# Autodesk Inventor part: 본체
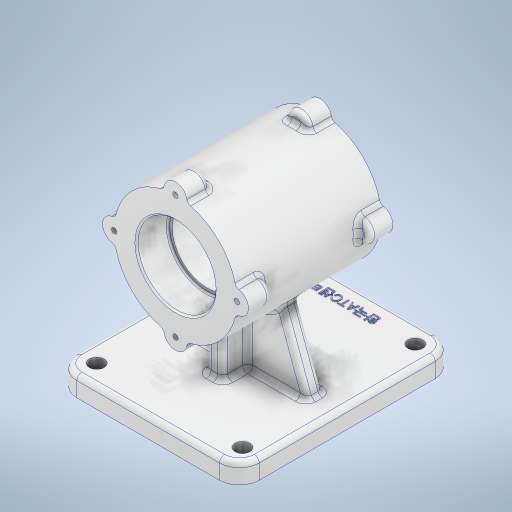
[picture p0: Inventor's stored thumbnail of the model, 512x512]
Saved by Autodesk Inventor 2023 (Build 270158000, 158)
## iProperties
Created: 2023-08
Part Number: 본체
Material: 알루미늄 6061
Document SubType Name: Modeling
Designer: asung
Density: 2.7 g/cm^3
Appearance: 알루미늄 - 평지
Author: asung
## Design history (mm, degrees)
sketch "스케치1"
  geometry: L1 (43, 65)-(-43, 65); L2 (-55, 53)-(-55, -53); L3 (-43, -65)-(43, -65); L4 (55, -53)-(55, 53); L5 (55, 65)-(-55, -65); L6 (-55, 65)-(55, -65); C1 r 4.5 at (43, -53); C2 r 4.5 at (43, 53); C3 r 4.5 at (-44.846, 53); C4 r 4.5 at (-43, -53); A1 r 12 centre (43, -53) between (43, -65) and (55, -53); A2 r 12 centre (43, 53) between (55, 53) and (43, 65); A3 r 12 centre (-43, 53) between (-43, 65) and (-55, 53); A4 r 12 centre (-43, -53) between (-55, -53) and (-43, -65); 1 further point
  constraints: 12 end point, 9 point on line, 8 centre point, 8 point on circle, 8 tangent, 3 coincident, 3 equal radius, 2 midpoint, 2 parallel, 1 horizontal, 1 perpendicular
  dimensions: "d0" = 110 distance of L6.end L5.end; "d1" = 130 distance of L5.end L6.start; "d2" = 12 radius of A1; "d3" = 9 diameter of C1; "d4" = 9 diameter of C2; "d5" = 9 diameter of C3; "d6" = 9 diameter of C4
extrude "돌출1" new body sketch "스케치1" distance "d7" = 12; taper "d8" = 0 deg
node "작업 평면1"
node "작업 평면2"
sketch "스케치2"
  geometry: L1 (98, 12)-(98, 0) reference; L2 (98, 0)-(-12, 0) reference; L3 (-12, 0)-(-12, 12) reference; L4 (-12, 12)-(98, 12) reference; L5 (43, 0)-(43, 82); L6 (43, 82)-(43, 52.403); L7 (43, -29.598)-(130, -29.598); C1 r 37 at (43, 82)
  constraints: 6 end point, 2 point on line, 1 centre point, 1 coincident, 1 horizontal, 1 vertical
  dimensions: "d10" = 82 distance of L5.start L5.end; "d11" = 87 distance of L7.start L7.end; "d12" = 37 radius of C1
extrude "돌출2" join sketch "스케치2" distance "d13" = 53.5; taper "d14" = 0 deg; dims "d65" = 33.5, "d66" = 0
sketch "스케치3"
  geometry: C1 r 7 at (0, 37); 6 further points
  constraints: 2 coincident, 1 centre point, 2 other
  dimensions: "d15" = 7 radius of C1
extrude "돌출3" join sketch "스케치3" distance "d16" = 14; taper "d17" = 0 deg
sketch "스케치4"
  geometry: A1 r 7 centre (43, 119) between (49.969, 118.338) and (36.031, 118.338) reference; 2 further points
  constraints: 1 coincident
hole "구멍1" sketch "스케치4" at (43, 119) diameter "d18" = 3.242; stored, may be unused: countersink angle "d22" = 90 deg, drill point angle "d24" = 118 deg; dims "d19" = 8, "d20" = 4, "d21" = 2, "d23" = 10
fillet "모깎기1" dims "d25" = 3
node "작업 평면3"
sketch "스케치6"
  geometry: A1 r 37 centre (-43, 82) between (-52.104, 117.863) and (-78.862, 91.104) reference; 4 further points
  constraints: 1 coincident
hole "구멍2" sketch "스케치6" at (-43, 82) diameter "d30" = 42; stored, may be unused: countersink angle "d34" = 90 deg, drill point angle "d36" = 118 deg; dims "d31" = 8, "d32" = 47, "d33" = 19, "d35" = 45
sketch "스케치7"
  geometry: A1 r 37 centre (43, 82) between (33.896, 117.863) and (7.137, 91.104) reference; 4 further points
  constraints: 1 coincident
hole "구멍3" sketch "스케치7" at (43, 82) diameter "d37" = 42; stored, may be unused: countersink angle "d41" = 90 deg, drill point angle "d43" = 118 deg; dims "d38" = 6, "d39" = 47, "d40" = 19, "d42" = 45
chamfer "모따기1" distance "d45" = 1; stored, may be unused: second distance "d46" = 2, angle "d47" = 45 deg
fillet "모깎기3" dims "d48" = 1
node "작업 평면4"
sketch "스케치8"
  geometry: L1 (-43, 65)-(43, 65) reference; L2 (55, 53)-(55, -53) reference; L3 (43, -65)-(-43, -65) reference; L4 (-55, -53)-(-55, 53) reference; L5 (5, 20)-(-5, 20); L6 (-5, 20)-(-5, -20); L7 (-5, -20)-(5, -20); L8 (5, -20)-(5, 20); L9 (5, 20)-(-5, -20); L10 (-5, 20)-(5, -20); C1 r 4.5 at (43, -53) reference; C2 r 4.5 at (43, 53) reference; C3 r 4.5 at (-44.846, 53) reference; C4 r 4.5 at (-43, -53) reference; A1 r 12 centre (43, 53) between (55, 53) and (43, 65) reference; A2 r 12 centre (43, -53) between (43, -65) and (55, -53) reference; A3 r 12 centre (-43, -53) between (-55, -53) and (-43, -65) reference; A4 r 12 centre (-43, 53) between (-43, 65) and (-55, 53) reference; 1 further point
  constraints: 12 end point, 2 midpoint, 2 parallel, 1 horizontal, 1 perpendicular
  dimensions: "d50" = 40 distance of L6.end L5.end; "d51" = 10 distance of L5.start L5.end
  node "절단 모서리 투영2"
fillet "모깎기4" dims "d54" = 3
sketch "스케치9"
  geometry: L1 (-52, -70)-(52, -70) reference; L2 (55, -73)-(55, -82) reference; L3 (55, -82)-(-55, -82) reference; L4 (-55, -82)-(-55, -73) reference; L5 (-43, -82)-(-55, -82) reference; L6 (-55, -82)-(-40.858, -82); L7 (43, -82)-(-43, -82) reference; L8 (-55, -82)-(-41, -82); L9 (-38.163, -74.206)-(-20.228, -24.929); L10 (0, -30.602)-(0, -82); L11 (38.163, -74.206)-(20.228, -24.929); L12 (-20.228, -24.929)-(-6.969, -29.755); L13 (-6.969, -29.755)-(20.228, -24.929); L14 (-38.163, -74.206)-(38.163, -74.206); C1 r 37 at (0, 0) reference; C2 r 21 at (0, 0) reference; A1 r 3 centre (-52, -73) between (-52, -70) and (-55, -73) reference; A2 r 3 centre (52, -73) between (55, -73) and (52, -70) reference; 1 further point
  constraints: 16 end point, 3 point on line, 2 symmetric about line, 1 horizontal, 1 vertical
  dimensions: "d55" = 14 distance of L3.end L8.end; "d56" = 110 deg angle of L9 L8
  node "절단 모서리 투영3"
sketch "스케치10"
  geometry: L1 (-52, -53)-(-52, 53) reference; L2 (-52, 0)-(-52, 58); L3 (-52, 58)-(0, 58); 2 further points
  constraints: 4 end point, 1 coincident, 1 collinear, 1 midpoint, 1 perpendicular
  dimensions: "d61" = 58 distance of L2.start L2.end
sketch "스케치11"
  geometry: L1 (-47.091, 5.14)-(-47.091, 63.14); 1 further point
  constraints: 2 end point, 1 vertical
  dimensions: "d62" = 58 distance of L1.start L1.end
node "작업 평면5"
sketch "스케치12"
  geometry: L1 (90.526, 45)-(91.5, 43.379) reference; L2 (91.5, 43.379)-(101.5, 43.379) reference; L3 (101.5, 43.379)-(101.5, 38) reference; L4 (101.5, 38)-(90.5, 38) reference; L5 (87.5, 41)-(87.5, 42) reference; L6 (84.5, 45)-(31.5, 45) reference; L7 (-9, 12)-(115, 12) reference; L8 (118, 9)-(118, 0) reference; L9 (118, 0)-(-12, 0) reference; L10 (-12, 0)-(-12, 9) reference; L11 (28.5, 42)-(28.5, 41) reference; L12 (25.5, 38)-(14.5, 38) reference; L13 (14.5, 38)-(14.5, 43.379) reference; L14 (14.5, 43.379)-(24.5, 43.379) reference; L15 (24.5, 43.379)-(25.474, 45) reference; L16 (25.474, 45)-(24.5, 46.621) reference; L17 (24.5, 46.621)-(14.5, 46.621) reference; L18 (14.5, 46.621)-(14.5, 57.5) reference; L19 (14.5, 57.5)-(15.5, 58.5) reference; L20 (15.5, 58.5)-(32.5, 58.5) reference; L21 (33.5, 59.5)-(33.5, 61) reference; L22 (33.5, 61)-(82.5, 61) reference; L23 (82.5, 61)-(82.5, 59.5) reference; L24 (83.5, 58.5)-(100.5, 58.5) reference; L25 (100.5, 58.5)-(101.5, 57.5) reference; L26 (101.5, 57.5)-(101.5, 46.621) reference; L27 (101.5, 46.621)-(91.5, 46.621) reference; L28 (91.5, 46.621)-(90.526, 45) reference; L29 (91.5, 120.621)-(90.526, 119) reference; L30 (90.526, 119)-(91.5, 117.379) reference; L31 (91.5, 117.379)-(101.5, 117.379) reference; L32 (101.5, 117.379)-(101.5, 106.5) reference; L33 (101.5, 106.5)-(100.5, 105.5) reference; L34 (100.5, 105.5)-(83.5, 105.5) reference; L35 (82.5, 104.5)-(82.5, 103) reference; L36 (82.5, 103)-(33.5, 103) reference; L37 (33.5, 103)-(33.5, 104.5) reference; L38 (32.5, 105.5)-(15.5, 105.5) reference; L39 (15.5, 105.5)-(14.5, 106.5) reference; L40 (14.5, 106.5)-(14.5, 117.379) reference; L41 (14.5, 117.379)-(24.5, 117.379) reference; L42 (24.5, 117.379)-(25.474, 119) reference; L43 (25.474, 119)-(24.5, 120.621) reference; L44 (24.5, 120.621)-(14.5, 120.621) reference; L45 (14.5, 120.621)-(14.5, 126) reference; L46 (14.5, 126)-(25.5, 126) reference; L47 (28.5, 123)-(28.5, 122) reference; L48 (31.5, 119)-(84.5, 119) reference; L49 (87.5, 122)-(87.5, 123) reference; L50 (90.5, 126)-(101.5, 126) reference; L51 (101.5, 126)-(101.5, 120.621) reference; L52 (101.5, 120.621)-(91.5, 120.621) reference; L53 (38, 54.414)-(78, 54.414); L54 (78, 54.414)-(78, 5.894); L55 (78, 5.894)-(38, 5.894); L56 (38, 5.894)-(38, 54.414); A1 r 3 centre (90.5, 41) between (87.5, 41) and (90.5, 38) reference; A2 r 3 centre (84.5, 42) between (87.5, 42) and (84.5, 45) reference; A3 r 3 centre (115, 9) between (118, 9) and (115, 12) reference; A4 r 3 centre (-9, 9) between (-9, 12) and (-12, 9) reference; A5 r 3 centre (31.5, 42) between (31.5, 45) and (28.5, 42) reference; A6 r 3 centre (25.5, 41) between (25.5, 38) and (28.5, 41) reference; A7 r 1 centre (32.5, 59.5) between (32.5, 58.5) and (33.5, 59.5) reference; A8 r 1 centre (83.5, 59.5) between (82.5, 59.5) and (83.5, 58.5) reference; A9 r 1 centre (83.5, 104.5) between (83.5, 105.5) and (82.5, 104.5) reference; A10 r 1 centre (32.5, 104.5) between (33.5, 104.5) and (32.5, 105.5) reference; A11 r 3 centre (25.5, 123) between (28.5, 123) and (25.5, 126) reference; A12 r 3 centre (31.5, 122) between (28.5, 122) and (31.5, 119) reference; A13 r 3 centre (84.5, 122) between (84.5, 119) and (87.5, 122) reference; A14 r 3 centre (90.5, 123) between (90.5, 126) and (87.5, 123) reference; 5 further points
  constraints: 8 end point, 2 parallel, 1 horizontal, 1 perpendicular
  dimensions: "d63" = 40 distance of L54.end L55.end; "d64" = 50 distance from line of L9.end L56
  node "절단 모서리 투영4"
node "작업 평면6"
sketch "스케치13"
  geometry: 1 further point
extrude "돌출7" join sketch "스케치12" stored distance "d69" = 10; taper "d70" = 0 deg
sketch "스케치14"
  geometry: L1 (-95, 12)-(-48, 12) reference; L2 (-48, 12)-(-48, 45.339) reference; L3 (-38, 45.339)-(-38, 12) reference; L4 (-38, 12)-(9, 12) reference; L5 (12, 9)-(12, 0) reference; L6 (12, 0)-(-98, 0) reference; L7 (-98, 0)-(-98, 9) reference; L8 (-98, 0)-(-98, 9) reference; L9 (-98, 9)-(-84, 9); L10 (-84, 9)-(-84, 12); L11 (-92.346, 12)-(-83.346, 12) reference; L12 (-84, 12)-(-63.719, 67.721); L13 (-43, 82)-(-43, 75.844); L14 (-2, 12)-(-22.281, 67.721); L15 (-63.719, 67.721)-(-48, 50.336); L16 (-48, 50.336)-(-37.401, 54.049); L17 (-37.401, 54.049)-(-22.281, 67.721); L18 (-84, 12)-(-2, 12); L19 (-86, 12)-(0, 12) reference; C1 r 21 at (-43, 82) reference; A1 r 3 centre (-95, 9) between (-95, 12) and (-98, 9) reference; A2 r 37 centre (-43, 82) between (-38, 45.339) and (-48, 45.339) reference; A3 r 3 centre (9, 9) between (12, 9) and (9, 12) reference; 5 further points
  constraints: 18 end point, 2 perpendicular, 2 symmetric about line, 1 collinear, 1 horizontal, 1 point on line, 1 vertical
  dimensions: "d71" = 14 distance of L7.end L9.end; "d72" = 110 deg angle of L12 L11
extrude "돌출8" join sketch "스케치14" stored distance "d73" = 10; taper "d74" = 0 deg
fillet "모깎기7" dims "d75" = 3
fillet "모깎기8" dims "d76" = 3
sketch "스케치16"
  geometry: L1 (-43, -65)-(43, -65) reference; 2 further points
  constraints: 1 vertical alignment, 1 other
  dimensions: "d81" = 118 distance from line of point (0, 53) L1
feature "엠보싱2" sketch "스케치16" dims "d0" = 110, "d1" = 130, "d2" = 12, "d3" = 9, "d4" = 9, "d5" = 9, "d6" = 9, "d82" = 0.5, "d83" = 0
feature "ӌ耀ӎ耀Ӑ耀Ӓ耀Ӕ耀Ӗ耀Ә耀Ӛ耀" dims "d0" = 110, "d1" = 130, "d2" = 12, "d3" = 9, "d4" = 9, "d5" = 9, "d6" = 9, "d7" = 12, "d8" = 0, "d9" = -70, "d10" = 82, "d11" = 87, "d12" = 37, "d13" = 53.5, "d14" = 0, "d15" = 7, "d16" = 14, "d17" = 0, "d18" = 3.242, "d19" = 8, "d20" = 4, "d21" = 2, "d22" = 90 deg, "d23" = 10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
node "솔리드1"
pattern_circular "원형 패턴1" dims angle "d27" = 360 deg
mirror "미러1"
node "절단 모서리 투영1"
node "절단 모서리 투영5"
feature "A9D066F2-1C7D-4E18-AEED-F7BC21143FA4" dims "d30" = 42, "d31" = 8, "d32" = 47, "d33" = 19, "d34" = 90 deg, "d35" = 45, "d36" = 118 deg
